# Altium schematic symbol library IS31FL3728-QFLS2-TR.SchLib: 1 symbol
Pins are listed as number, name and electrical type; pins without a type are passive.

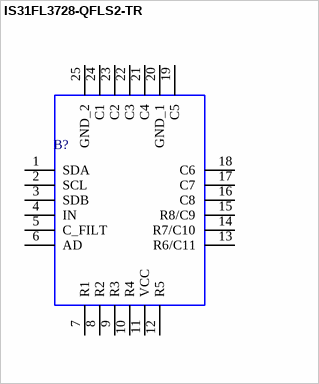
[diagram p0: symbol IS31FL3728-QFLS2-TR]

## IS31FL3728-QFLS2-TR
designator B?
LED Lighting Drivers Audio Mod Matrix LED Driver; Manufacturer_Name: Integrated Silicon Solution Inc.; Geometry.Height: 0.8mm
footprint QFN50P400X400X80-25N-D
pins: 1 SDA, 2 SCL, 3 SDB, 4 IN, 5 C_FILT, 6 AD, 7 R1, 8 R2, 9 R3, 10 R4, 11 VCC, 12 R5, 13 R6/C11, 14 R7/C10, 15 R8/C9, 16 C8, 17 C7, 18 C6, 19 C5, 20 GND_1, 21 C4, 22 C3, 23 C2, 24 C1, 25 GND_2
